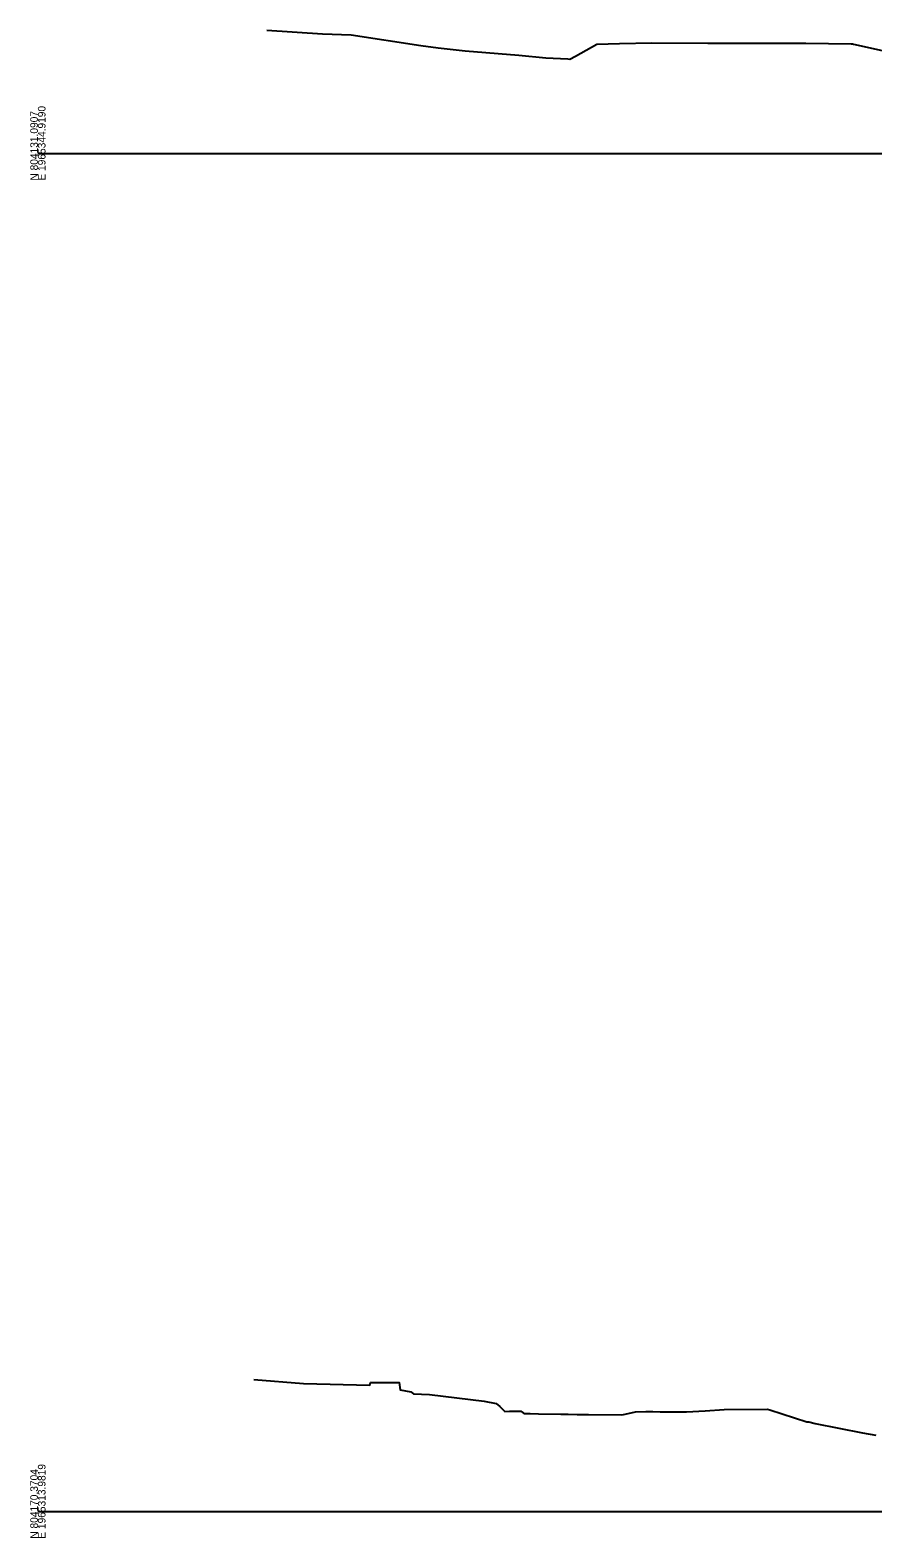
# Model space of a CAD drawing. Extents: x 1017 to 19997, y -1947 to 50737.
# Drawn here: x 11997 to 12307, y 13990 to 14545 of the extents above; entities that cross this region are included whole.
import ezdxf

# ---------------------------------------------------------------- set-up
doc = ezdxf.new("R2010")
doc.units = 0
for name, color, linetype in [('Default', 7, 'Continuous'), ('RD_GPK_XS_Cell', 7, 'Continuous'), ('RD_XS_ExGround', 7, 'Continuous')]:
    doc.layers.add(name, color=color, linetype=linetype)

msp = doc.modelspace()

# ---------------------------------------------------------------- linework, layer by layer
at = {"layer": 'RD_GPK_XS_Cell'}
for p, q in [((12000, 14500), (12600, 14500)), ((12000, 14000), (12600, 14000))]:
    msp.add_line(p, q, dxfattribs=at)
at = {"layer": 'RD_XS_ExGround'}
for points in [[(12084.27, 14545.38), (12104.75, 14544.06), (12115.31, 14543.61), (12140.85, 14539.76), (12147.27, 14538.86), (12150.57, 14538.45), (12157.26, 14537.72), (12177.01, 14536.13), (12186.86, 14535.23), (12194.98, 14534.78), (12195.69, 14534.7), (12197.8, 14535.8), (12205.7, 14540.17), (12214.05, 14540.46), (12225.88, 14540.76), (12246.49, 14540.58), (12254.95, 14540.55), (12275.85, 14540.55), (12282.56, 14540.58), (12299.28, 14540.36), (12299.68, 14540.36), (12300.11, 14540.26), (12310.66, 14537.85)], [(12079.47, 14048.58), (12097.78, 14047.07), (12122.12, 14046.47), (12122.33, 14047.48), (12129.87, 14047.48), (12132.91, 14047.48), (12133.33, 14044.77), (12137.16, 14044.06), (12138.15, 14043.38), (12144.03, 14043.13), (12164.25, 14040.64), (12168.63, 14039.72), (12169.94, 14038.63), (12171.77, 14036.82), (12173.57, 14036.9), (12177.68, 14036.99), (12178.58, 14036.32), (12179.07, 14036.04), (12181.07, 14036.06), (12184.2, 14036), (12192.41, 14035.87), (12195.14, 14035.8), (12198.41, 14035.72), (12200.31, 14035.71), (12202.58, 14035.73), (12214.81, 14035.57), (12216.03, 14035.82), (12219.86, 14036.68), (12223.66, 14036.81), (12226.27, 14036.83), (12228.99, 14036.69), (12233.28, 14036.68), (12233.87, 14036.68), (12235.81, 14036.67), (12238.07, 14036.67), (12238.62, 14036.67), (12245.55, 14037.09), (12252.51, 14037.6), (12268.34, 14037.72), (12269.29, 14037.4), (12282.87, 14033), (12283.68, 14033.01), (12285.98, 14032.37), (12303.38, 14028.98), (12308.31, 14028.06)]]:
    msp.add_lwpolyline(points, dxfattribs=at)

# ---------------------------------------------------------------- texts
at = {"layer": 'Default'}
for p in [(12000, 14500), (12000, 14000)]:
    msp.add_text('-', height=0.0001, dxfattribs=at).set_placement(p)
at = {"layer": 'RD_GPK_XS_Cell'}
for s, p in [('N 804131.0907', (12000, 14490)), ('E 1965344.9190', (12002.8, 14490)), ('E 1965313.9819', (12002.8, 13990)), ('N 804170.3704', (12000, 13990))]:
    msp.add_text(s, height=2.8, rotation=90, dxfattribs=at).set_placement(p)

doc.saveas('drawing.dxf')
